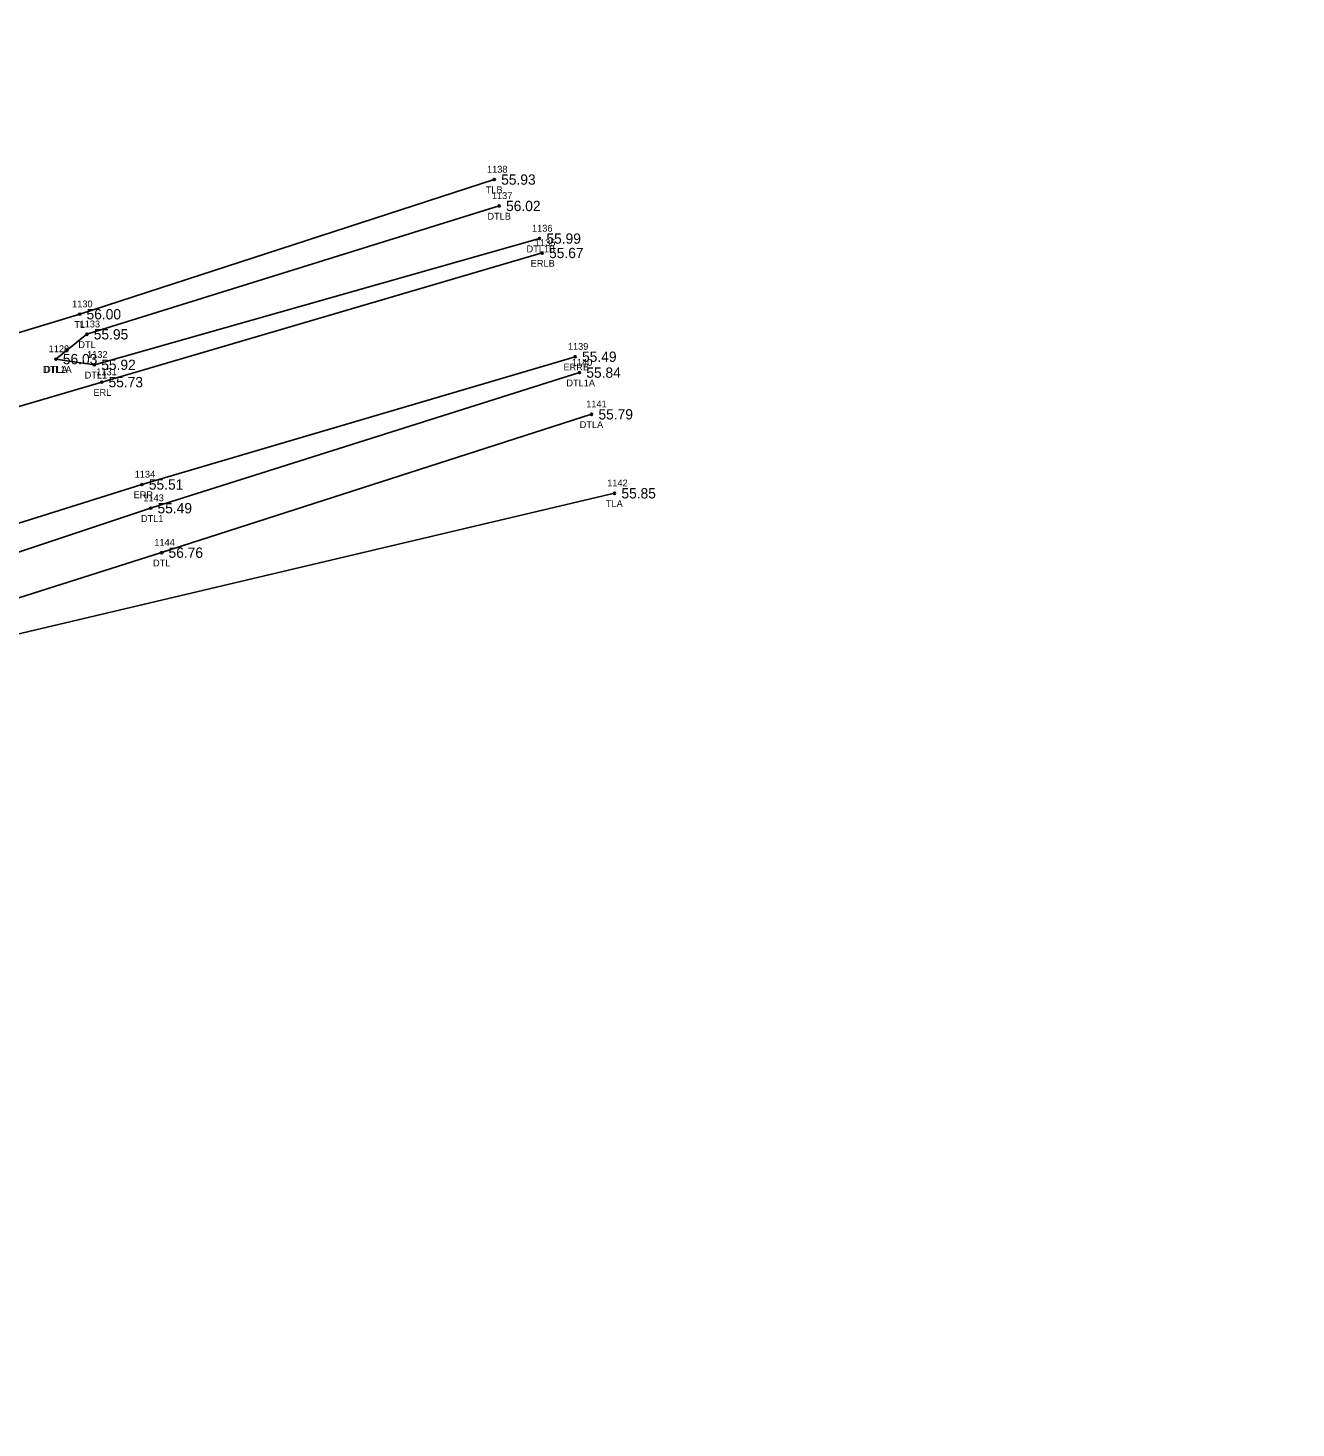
# Model space of a CAD drawing. Extents: x 2396531 to 2397633, y 770203 to 772837.
# Drawn here: x 2397051.8 to 2397236.4, y 771574.1 to 771777.9 of the extents above; entities that cross this region are included whole.
import ezdxf

# ---------------------------------------------------------------- set-up
doc = ezdxf.new("R2010")
doc.units = 0
for name, color, linetype in [('RD_EX_H2O', 7, 'Continuous'), ('RD_EX_H2O_txCode', 7, 'Continuous'), ('RD_EX_Road', 7, 'Continuous'), ('RD_EX_Road_txCode', 7, 'Continuous'), ('RD_EX_TX_H2O_ELEV', 7, 'Continuous'), ('RD_EX_TX_Road_ELEV', 7, 'Continuous'), ('RD_EX_TX_VEG_ELEV', 7, 'Continuous'), ('RD_EX_VEG', 7, 'Continuous'), ('RD_EX_VEG_txCode', 7, 'Continuous'), ('RD_SMD_Locator', 7, 'Continuous')]:
    doc.layers.add(name, color=color, linetype=linetype)

msp = doc.modelspace()

# ---------------------------------------------------------------- linework, layer by layer
at = {"layer": 'RD_EX_H2O'}
for points in [[(2397055.87, 771729.7), (2397060.37, 771733.31), (2397120.38, 771752)], [(2397055.87, 771729.7), (2397061.46, 771728.87), (2397126.25, 771747.25)], [(2397132.06, 771727.73), (2397069.65, 771707.99), (2397027.41, 771693.94), (2396997.29, 771683.71), (2397009.52, 771621.94), (2397039.8, 771510.33), (2397059.22, 771428.3), (2397068.26, 771415.82), (2397065.8, 771409.74)], [(2397133.83, 771721.66), (2397071.25, 771701.52), (2397031.62, 771688.97), (2397008.91, 771681.79), (2397013.82, 771672.05), (2397025.11, 771625.88), (2397054.64, 771514.68), (2397075.97, 771429.94), (2397072.44, 771413.81)]]:
    msp.add_lwpolyline(points, dxfattribs=at)
at = {"layer": 'RD_EX_Road'}
for points in [[(2396998.08, 771710.28), (2397032.74, 771717.63), (2397062.52, 771726.35), (2397126.64, 771745.15)], [(2397002.95, 771693.12), (2397036.69, 771701.48), (2397068.39, 771711.44), (2397131.44, 771730.05)]]:
    msp.add_lwpolyline(points, dxfattribs=at)
at = {"layer": 'RD_EX_VEG'}
for points in [[(2396927.91, 772008.32), (2396999.71, 771718.21), (2397059.32, 771736.23), (2397119.67, 771755.84)], [(2397137.17, 771710.16), (2397010.6, 771680.28), (2397078.29, 771429.37), (2397127.02, 771232.69), (2397127.02, 771232.69), (2397166.52, 771123.83), (2397178.02, 771098.29), (2397254.06, 771102.5)]]:
    msp.add_lwpolyline(points, dxfattribs=at)
at = {"layer": 'RD_SMD_Locator'}
for centre in [(2397119.67, 771755.84), (2397120.38, 771752), (2397126.25, 771747.25), (2397126.64, 771745.15), (2397059.32, 771736.23), (2397060.37, 771733.31), (2397131.44, 771730.05), (2397055.87, 771729.7), (2397055.87, 771729.7), (2397061.46, 771728.87), (2397132.06, 771727.73), (2397062.52, 771726.35), (2397133.83, 771721.66), (2397068.39, 771711.44), (2397137.17, 771710.16), (2397069.65, 771707.99), (2397071.25, 771701.52)]:
    msp.add_circle(centre, 0.15, dxfattribs=at)

# ---------------------------------------------------------------- texts
at = {"layer": 'RD_EX_H2O_txCode'}
for s, p in [('1137', (2397119.32, 771753)), ('DTLB', (2397118.67, 771750)), ('1136', (2397125.16, 771748.25)), ('DTL1B', (2397124.36, 771745.25)), ('1133', (2397059.31, 771734.31)), ('DTL', (2397059.13, 771731.31)), ('1128', (2397054.81, 771730.7)), ('1129', (2397054.81, 771730.7)), ('1132', (2397060.4, 771729.87)), ('DTL1A', (2397053.98, 771727.7)), ('DTLA', (2397054.14, 771727.7)), ('DTL1', (2397060.05, 771726.87)), ('1140', (2397130.96, 771728.73)), ('DTL1A', (2397130.16, 771725.73)), ('1141', (2397133.05, 771722.66)), ('DTLA', (2397132.1, 771719.66)), ('1143', (2397068.59, 771708.99)), ('DTL1', (2397068.24, 771705.99)), ('1144', (2397070.19, 771702.52)), ('DTL', (2397070, 771699.52))]:
    msp.add_text(s, height=1, dxfattribs=at).set_placement(p)
at = {"layer": 'RD_EX_Road_txCode'}
for s, p in [('1135', (2397125.58, 771746.15)), ('ERLB', (2397124.97, 771743.15)), ('1139', (2397130.38, 771731.05)), ('1131', (2397061.74, 771727.35)), ('ERRB', (2397129.74, 771728.05)), ('ERL', (2397061.32, 771724.35)), ('1134', (2397067.33, 771712.44)), ('ERR', (2397067.17, 771709.44))]:
    msp.add_text(s, height=1, dxfattribs=at).set_placement(p)
at = {"layer": 'RD_EX_TX_H2O_ELEV'}
for s, p in [('56.02', (2397121.38, 771751.25)), ('55.99', (2397127.25, 771746.5)), ('55.95', (2397061.37, 771732.56)), ('56.03', (2397056.87, 771728.95)), ('56.03', (2397056.87, 771728.95)), ('55.92', (2397062.46, 771728.12)), ('55.84', (2397133.06, 771726.98)), ('55.79', (2397134.83, 771720.91)), ('55.49', (2397070.65, 771707.24)), ('56.76', (2397072.25, 771700.77))]:
    msp.add_text(s, height=1.5, dxfattribs=at).set_placement(p)
at = {"layer": 'RD_EX_TX_Road_ELEV'}
for s, p in [('55.67', (2397127.64, 771744.4)), ('55.49', (2397132.44, 771729.3)), ('55.73', (2397063.52, 771725.6)), ('55.51', (2397069.39, 771710.69))]:
    msp.add_text(s, height=1.5, dxfattribs=at).set_placement(p)
at = {"layer": 'RD_EX_TX_VEG_ELEV'}
for s, p in [('55.93', (2397120.67, 771755.09)), ('56.00', (2397060.32, 771735.48)), ('55.85', (2397138.17, 771709.41))]:
    msp.add_text(s, height=1.5, dxfattribs=at).set_placement(p)
at = {"layer": 'RD_EX_VEG_txCode'}
for s, p in [('1138', (2397118.61, 771756.84)), ('TLB', (2397118.43, 771753.84)), ('1130', (2397058.22, 771737.23)), ('TL', (2397058.55, 771734.23)), ('1142', (2397136.1, 771711.16)), ('TLA', (2397135.91, 771708.16))]:
    msp.add_text(s, height=1, dxfattribs=at).set_placement(p)

doc.saveas('drawing.dxf')
